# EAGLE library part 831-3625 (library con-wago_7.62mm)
Serie 831, Stiftleiste (für Leiterplatten) mit abgewinkelten Einlötstiften / Series 831, Male header (for PCBs) with angled solder pins Polzahl / Pole No.: 5 Bemessungsspannung / Rated Voltage: 630 V Nennstrom / Nominal Current: 41 A Lötstiftlänge: / Solder Pin Length: 4 mm Farbe / Color: lichtgrau / light gray Stand: 01.01.2012. Die jeweils aktuellen Daten zu diesem Artikel finden Sie in unserem Produktkatalog, den Sie unter www.wago.com einsehen können. As of: 01/01/2012. Please find the newest data for this article in our product catalogue, which can be viewed under www.wago.com.
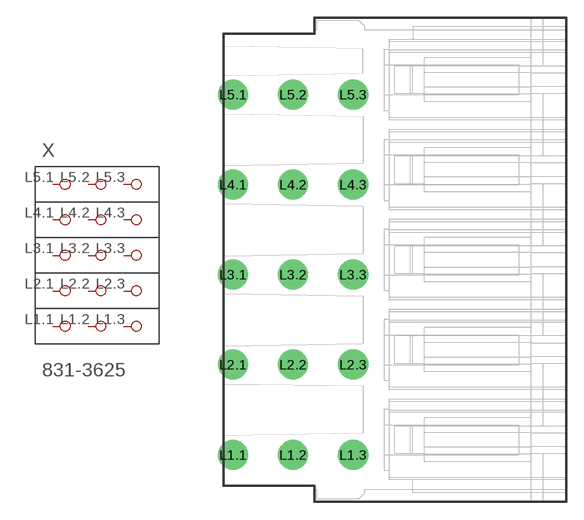
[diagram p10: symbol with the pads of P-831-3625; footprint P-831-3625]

Designator prefix X

## 831-3625  [P-831-3625]
L1.1  P1.1
L1.2  P1.2
L1.3  P1.3
L2.1  P2.1
L2.2  P2.2
L2.3  P2.3
L3.1  P3.1
L3.2  P3.2
L3.3  P3.3
L4.1  P4.1
L4.2  P4.2
L4.3  P4.3
L5.1  P5.1
L5.2  P5.2
L5.3  P5.3

## Footprint P-831-3625 (pad centres in mm)
drill 1.7 round: L1.1 -13.7,-16.51; L1.2 -8.62,-16.51; L1.3 -3.54,-16.51; L2.1 -13.7,-8.87; L2.2 -8.62,-8.87; L2.3 -3.54,-8.87; L3.1 -13.7,-1.25; L3.2 -8.62,-1.25; L3.3 -3.54,-1.25; L4.1 -13.7,6.37; L4.2 -8.62,6.37; L4.3 -3.54,6.37; L5.1 -13.7,13.99; L5.2 -8.62,13.99; L5.3 -3.54,13.99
